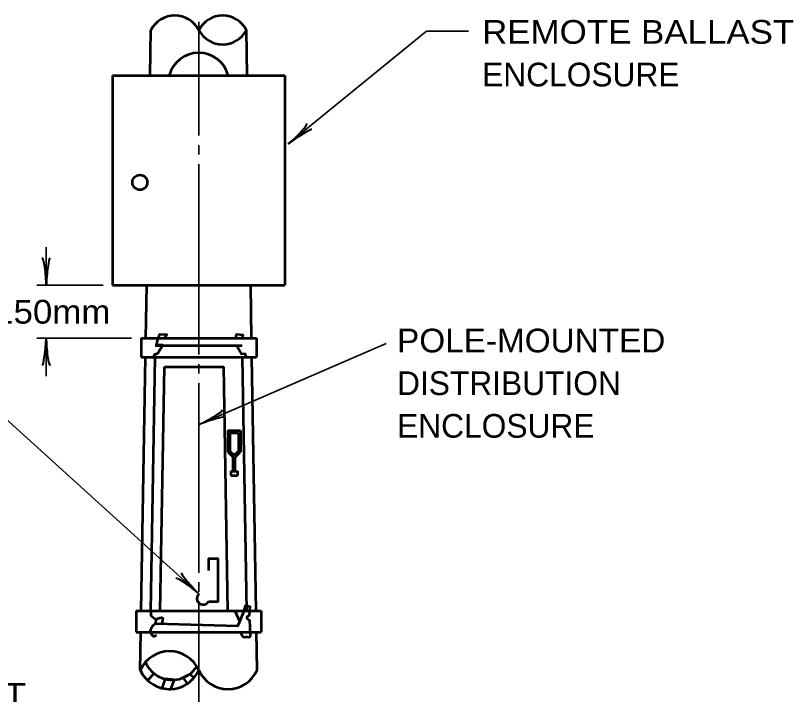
# Model space of a CAD drawing. Extents: x -111 to 744, y -77 to 467.
# Drawn here: x 209.8 to 308.2, y 256.6 to 342.5 of the extents above; entities that cross this region are included whole.
import ezdxf
from ezdxf.enums import TextEntityAlignment as Align

# ---------------------------------------------------------------- set-up
doc = ezdxf.new("R2010")
doc.units = 0
doc.header["$LTSCALE"] = 1.2
doc.layers.add('1', color=7, linetype='Continuous', lineweight=53)

msp = doc.modelspace()

# ---------------------------------------------------------------- linework, layer by layer
at = {"layer": '1', "lineweight": 35}
for p, q in [((232.939, 341.68), (232.939, 327.28)), ((232.939, 326.079), (232.939, 324.88)), ((232.939, 323.68), (232.939, 299.568)), ((213.646, 308.364), (213.646, 313.164)), ((220.846, 308.364), (212.446, 308.364)), ((224.446, 301.639), (212.446, 301.639)), ((213.646, 301.639), (213.646, 296.839)), ((232.978, 290.736), (256.664, 300.982)), ((232.939, 298.368), (232.939, 297.168)), ((232.939, 295.968), (232.939, 271.968)), ((232.956, 269.288), (208.049, 291.917)), ((232.939, 270.768), (232.939, 269.568)), ((232.939, 268.368), (232.939, 250.368))]:
    msp.add_line(p, q, dxfattribs=at)
at = {"layer": '1'}
for p, q in [((226.8, 334.894), (226.896, 340.65)), ((239.078, 334.894), (238.982, 340.65)), ((222.046, 334.894), (243.832, 334.894)), ((222.046, 334.894), (222.046, 308.364)), ((243.832, 334.894), (243.832, 308.364)), ((222.046, 308.364), (243.832, 308.364)), ((226.246, 301.639), (226.358, 308.364)), ((239.632, 301.639), (239.52, 308.364)), ((225.646, 301.639), (240.232, 301.639)), ((225.646, 301.639), (225.646, 299.239)), ((240.232, 301.639), (240.232, 299.239)), ((227.446, 300.739), (238.432, 300.739)), ((225.646, 299.239), (240.232, 299.239)), ((225.672, 267.139), (226.207, 299.239)), ((226.871, 267.139), (227.407, 299.239)), ((239.007, 267.139), (238.472, 299.239)), ((240.207, 267.139), (239.672, 299.239)), ((228.071, 267.119), (228.587, 298.039)), ((228.587, 298.039), (236.092, 298.039)), ((236.607, 267.099), (236.092, 298.039)), ((236.609, 289.952), (238.229, 289.952)), ((236.609, 289.952), (236.609, 287.252)), ((236.879, 289.683), (237.959, 289.683)), ((236.879, 289.683), (236.879, 287.364)), ((237.959, 289.683), (237.959, 287.364)), ((238.229, 289.952), (238.229, 287.252)), ((236.879, 287.364), (237.419, 286.824)), ((237.419, 286.824), (237.959, 287.364)), ((236.609, 287.252), (237.284, 286.577)), ((237.284, 284.822), (237.284, 286.577)), ((237.554, 286.577), (238.229, 287.252)), ((237.554, 284.822), (237.554, 286.577)), ((237.014, 284.822), (237.824, 284.822)), ((237.014, 284.822), (237.014, 284.283)), ((237.824, 284.822), (237.824, 284.283)), ((237.014, 284.283), (237.824, 284.283)), ((225.026, 267.139), (240.852, 267.139)), ((225.026, 267.139), (225.026, 264.439)), ((238.149, 265.797), (238.694, 267.161)), ((240.852, 267.139), (240.852, 264.439)), ((239.343, 265.987), (239.444, 264.16)), ((225.026, 264.439), (240.852, 264.439)), ((225.546, 259.639), (225.626, 264.439)), ((240.332, 259.639), (240.252, 264.439)), ((226.502, 258.31), (227.268, 259.23)), ((231.793, 259.148), (232.368, 258.717)), ((228.693, 258.522), (228.278, 257.359)), ((231.535, 257.953), (230.971, 258.705)), ((231.535, 257.953), (230.971, 258.705)), ((231.535, 257.953), (230.971, 258.705)), ((231.535, 257.953), (230.971, 258.705))]:
    msp.add_line(p, q, dxfattribs=at)
at = {"layer": '1', "lineweight": 13}
msp.add_line((236.239, 267.168), (231.739, 267.168), dxfattribs=at)
at = {"layer": '1', "lineweight": 35}
msp.add_lwpolyline([(244.265, 326.245), (261.736, 340.499), (267.043, 340.499)], dxfattribs=at)
at = {"layer": '1'}
for points in [[(227.407, 299.239), (227.302, 299.522), (227.747, 299.745), (228.383, 300.747), (227.604, 300.747), (227.763, 301.495), (228.001, 302.147), (228.923, 302.131), (228.621, 301.654)], [(237.621, 301.654), (237.732, 302.163), (238.511, 302.067), (238.431, 301.701)], [(238.472, 299.239), (238.956, 299.331), (238.829, 299.681), (238.352, 299.634), (237.716, 300.715)], [(234.187, 268.339), (235.387, 268.339), (235.387, 273.739), (234.187, 273.739), (234.187, 272.239)], [(238.694, 267.161), (238.853, 267.82), (239.421, 267.707), (239.331, 266.57)], [(226.871, 267.139), (226.897, 266.547), (227.511, 266.047), (227.465, 265.524), (237.899, 265.228), (238.149, 265.797), (237.535, 267.116)], [(231.535, 257.953), (230.971, 258.705), (231.793, 259.148)], [(229.427, 257.246), (229.875, 258.413), (228.693, 258.522)]]:
    msp.add_lwpolyline(points, dxfattribs=at)
msp.add_circle((225.49, 321.362), 0.942, dxfattribs=at)
for centre, radius, start, end in [((229.917, 339.073), 3.408, 27.5646, 152.44109), ((235.96, 339.073), 3.408, 27.5646, 152.44109), ((235.96, 342.227), 3.408, 207.55891, 332.4354), ((232.939, 333.903), 3.868, 14.84165, 165.15835), ((233.496, 268.716), 0.787, 133.35439, 331.33852), ((229.243, 257.987), 4.049, 24.07948, 155.9231), ((229.243, 257.987), 4.049, 138.90512, 155.92052), ((229.583, 262.103), 3.69, 203.21853, 231.14333), ((229.583, 262.103), 3.69, 306.79311, 327.33243), ((229.243, 261.291), 4.049, 204.07948, 272.59979), ((229.243, 261.291), 4.049, 204.07948, 227.39786), ((229.583, 262.103), 3.69, 231.14333, 256.04211), ((229.583, 262.103), 3.69, 292.29814, 306.79311), ((229.243, 261.291), 4.049, 320.52562, 335.92052), ((236.636, 261.291), 4.049, 204.07948, 335.92052), ((229.583, 262.103), 3.69, 256.04211, 274.61107), ((229.243, 261.291), 4.049, 272.59984, 320.52559), ((229.583, 262.103), 3.69, 274.61107, 292.29814), ((229.243, 261.291), 4.049, 304.47948, 320.52562), ((229.243, 261.291), 4.049, 256.20747, 272.59984)]:
    msp.add_arc(centre, radius, start, end, dxfattribs=at)
at = {"layer": '1', "lineweight": 40}
for centre, major_axis, ratio, start_param, end_param in [((245.07, 327.329), (-1.542, -1.5), 0.122415, 0.896353, 3.141593), ((245.467, 326.898), (-1.766, -1.169), 0.07063, 3.140715, 5.41811), ((213.315, 309.673), (0.187, -2.143), 0.122415, 0.896353, 3.141593), ((213.315, 309.673), (0.187, -2.143), 0.122415, 0.896353, 3.141593), ((213.9, 309.708), (-0.211, -2.108), 0.07063, 3.140715, 5.41811), ((213.9, 309.708), (-0.211, -2.108), 0.07063, 3.140715, 5.41811), ((213.392, 300.294), (0.211, 2.108), 0.07063, 3.140715, 5.41811), ((213.978, 300.329), (-0.187, 2.143), 0.122415, 0.896353, 3.141593), ((234.048, 291.56), (-1.892, -1.023), 0.122415, 0.896353, 3.141593), ((234.312, 291.037), (2.018, 0.643), 0.07063, 6.282307, 8.559703), ((232.131, 270.381), (-1.418, 1.573), 0.07063, 6.282307, 8.559703), ((231.764, 269.924), (1.712, -1.302), 0.122415, 0.896353, 3.141593)]:
    msp.add_ellipse(centre, major_axis=major_axis, ratio=ratio, start_param=start_param, end_param=end_param, dxfattribs=at)
at = {"layer": '1'}
for points in [[(227.511, 266.047), (228.352, 266.252), (228.261, 265.547)], [(239.331, 266.57), (239.012, 266.252), (239.353, 265.979)], [(227.465, 265.524), (227.329, 265.433), (226.965, 265.024), (226.806, 264.569), (226.92, 264.251), (227.215, 263.955), (227.579, 264.069)], [(239.444, 264.16), (239.399, 263.841), (238.99, 263.796), (238.603, 263.819), (238.421, 264.023), (238.353, 264.433)]]:
    msp.add_spline(points, degree=3, dxfattribs=at)

# ---------------------------------------------------------------- texts
for s, width, p in [('REMOTE BALLAST', 1.1, (268.779, 338.913)), ('POLE-MOUNTED', 1.05, (258.023, 299.853)), ('100mm CONDUIT', 1.15, (173.438, 255.015))]:
    msp.add_text(s, height=3, dxfattribs=dict(at, width=width)).set_placement(p)
for s, p in [('ENCLOSURE', (268.779, 333.513)), ('DISTRIBUTION', (258.023, 294.453)), ('ENCLOSURE', (258.023, 289.053))]:
    msp.add_text(s, height=3, dxfattribs=at).set_placement(p)
at = {"layer": '1', "width": 1.1}
msp.add_text('150mm', height=3, dxfattribs=at).set_placement((214.413, 303.491), align=Align.CENTER)

doc.saveas('drawing.dxf')
